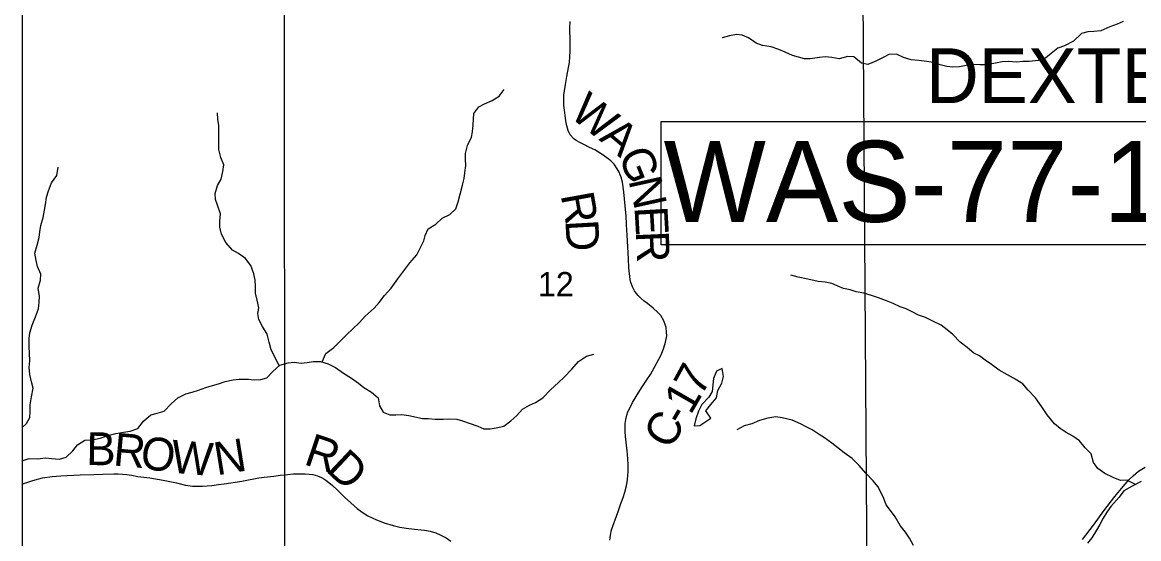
# Model space of a CAD drawing. Extents: x 0 to 34, y 0 to 22.
# Drawn here: x 2.1 to 4.027, y 17.434 to 18.326 of the extents above; entities that cross this region are included whole.
import ezdxf

# ---------------------------------------------------------------- set-up
doc = ezdxf.new("R2010")
doc.units = 0
for name, color, linetype in [('Default', 7, 'Continuous'), ('GM_X_Corporation_Text', 7, 'Continuous'), ('GM_X_County_Road', 7, 'Continuous'), ('GM_X_County_Road_Text', 7, 'Continuous'), ('GM_X_Minor_Lake', 7, 'Continuous'), ('GM_X_Minor_River', 7, 'Continuous'), ('GM_X_Rail_Line', 7, 'Continuous'), ('GM_X_Section', 7, 'Continuous'), ('GM_X_Section_Text', 7, 'Continuous'), ('GM_X_State_Route', 7, 'Continuous'), ('GM_X_Township_Road', 7, 'Continuous'), ('GM_X_Township_Road_Text', 7, 'Continuous'), ('SH_Cut_Line', 7, 'Continuous'), ('SH_Data', 7, 'Continuous')]:
    doc.layers.add(name, color=color, linetype=linetype)

msp = doc.modelspace()

# ---------------------------------------------------------------- linework, layer by layer
at = {"layer": 'Default'}
for points in [[(2.1, 18.418), (2.1, 17.4114), (2.5532, 17.3998), (2.5522, 18.4023)], [(3.2025, 18.1545), (4.5002, 18.1545), (4.5002, 17.9419), (3.2025, 17.9419)]]:
    msp.add_lwpolyline(points, close=True, dxfattribs=at)
at = {"layer": 'GM_X_County_Road'}
msp.add_lwpolyline([(3.1137, 17.4319), (3.1151, 17.4405), (3.1171, 17.4495), (3.1276, 17.4792), (3.1297, 17.4848), (3.1323, 17.4931), (3.1367, 17.5056), (3.1397, 17.5146), (3.1425, 17.5257), (3.1443, 17.5365), (3.1457, 17.5501), (3.1458, 17.562), (3.1453, 17.5724), (3.1438, 17.5859), (3.141, 17.611), (3.1403, 17.619), (3.1403, 17.6267), (3.1406, 17.6334), (3.1416, 17.6403), (3.1434, 17.6476), (3.1453, 17.6531), (3.1483, 17.6594), (3.1533, 17.6694), (3.161, 17.6829), (3.1685, 17.6949), (3.178, 17.7085), (3.1842, 17.718), (3.1913, 17.7307), (3.1985, 17.7445), (3.2029, 17.7531), (3.2071, 17.764), (3.2103, 17.7738), (3.2121, 17.7844), (3.212, 17.7911), (3.211, 17.7989), (3.2103, 17.8023), (3.2074, 17.8104), (3.2017, 17.8199), (3.1964, 17.8253), (3.1888, 17.8324), (3.1787, 17.8404), (3.173, 17.8447), (3.1679, 17.8491), (3.1629, 17.8545), (3.1596, 17.8585), (3.1567, 17.8624), (3.1536, 17.8682), (3.1504, 17.8766), (3.1491, 17.8821), (3.1469, 17.9021), (3.146, 17.9171), (3.1438, 17.9592), (3.1433, 17.9672), (3.1426, 17.9776), (3.1421, 17.9914), (3.1405, 18.009), (3.1379, 18.0335), (3.1357, 18.0502), (3.1333, 18.0586), (3.132, 18.0624), (3.13, 18.0671), (3.1268, 18.0732), (3.1212, 18.0808), (3.1155, 18.0868), (3.1089, 18.0922), (3.1009, 18.098), (3.0879, 18.1056), (3.079, 18.11), (3.0691, 18.1149), (3.0624, 18.1183), (3.0558, 18.1221), (3.0516, 18.1248), (3.0456, 18.1316), (3.0421, 18.139), (3.0395, 18.1472), (3.0379, 18.1558), (3.0355, 18.1742), (3.0347, 18.1824), (3.0343, 18.1939), (3.0347, 18.2003), (3.0356, 18.2077), (3.0373, 18.2185), (3.04, 18.2326), (3.0427, 18.248), (3.0441, 18.2568), (3.045, 18.2667), (3.0455, 18.2757), (3.0453, 18.2824), (3.0455, 18.2944), (3.0454, 18.3014), (3.0452, 18.3081), (3.0451, 18.3172), (3.0456, 18.3274)], dxfattribs=at)
at = {"layer": 'GM_X_Minor_Lake'}
for points in [[(3.2882, 17.6423), (3.2794, 17.6552), (3.2881, 17.6662), (3.298, 17.6777), (3.3006, 17.6902), (3.3073, 17.7031), (3.3103, 17.7145), (3.308, 17.7281), (3.3013, 17.725)], [(3.3013, 17.725), (3.2981, 17.7235), (3.2929, 17.711), (3.2907, 17.6882), (3.2847, 17.6784), (3.2726, 17.6662), (3.2669, 17.6544), (3.2624, 17.6415), (3.2594, 17.6289), (3.2693, 17.6297), (3.2882, 17.6423)]]:
    msp.add_lwpolyline(points, dxfattribs=at)
at = {"layer": 'GM_X_Minor_River'}
for points in [[(4.0001, 18.3273), (3.9895, 18.3227), (3.977, 18.318), (3.9615, 18.3111), (3.9493, 18.3103), (3.9387, 18.3094), (3.9277, 18.3067), (3.9141, 18.2937), (3.8986, 18.2853), (3.8869, 18.2814), (3.8759, 18.2719), (3.8657, 18.2642), (3.8532, 18.26), (3.8377, 18.2583), (3.8266, 18.2583), (3.816, 18.2574), (3.8012, 18.2585), (3.7913, 18.2577), (3.7769, 18.2549), (3.7629, 18.2525), (3.7523, 18.2525), (3.742, 18.2532), (3.7287, 18.2512), (3.7174, 18.2492), (3.706, 18.2488), (3.6957, 18.2498), (3.6839, 18.2524), (3.6717, 18.2569), (3.6611, 18.2583), (3.647, 18.2601), (3.6341, 18.2612), (3.6208, 18.2653), (3.6086, 18.2709), (3.5957, 18.2704), (3.5855, 18.265)], [(3.5855, 18.265), (3.573, 18.2589), (3.5594, 18.2531), (3.548, 18.2557), (3.535, 18.2662), (3.5247, 18.2669), (3.5096, 18.263), (3.497, 18.2652), (3.4856, 18.2663), (3.4758, 18.2655), (3.4598, 18.2627), (3.45, 18.263), (3.4393, 18.2656), (3.4294, 18.2686), (3.4165, 18.2742), (3.4054, 18.279), (3.3921, 18.2835), (3.3773, 18.2861), (3.3666, 18.2898), (3.3533, 18.2992), (3.3426, 18.304), (3.3324, 18.3047), (3.3202, 18.3028), (3.3077, 18.2993)], [(2.6172, 17.7396), (2.6239, 17.7538), (2.6378, 17.7645), (2.6472, 17.7741), (2.66, 17.7867), (2.6701, 17.7962), (2.6817, 17.8077), (2.6919, 17.8184), (2.7073, 17.8322), (2.7159, 17.8421), (2.7252, 17.854), (2.7365, 17.8669), (2.7481, 17.8833), (2.7585, 17.8971), (2.7686, 17.9104), (2.7806, 17.9246), (2.7862, 17.9348), (2.7929, 17.9485), (2.7951, 17.958), (2.8007, 17.9691), (2.8135, 17.9772), (2.8247, 17.9875), (2.8379, 17.994), (2.8481, 18.004), (2.8521, 18.0162), (2.8554, 18.0294), (2.8598, 18.0447), (2.8624, 18.0564), (2.8638, 18.0659), (2.8652, 18.0788), (2.8647, 18.0898), (2.865, 18.0997), (2.8683, 18.113), (2.8754, 18.1274), (2.8768, 18.1369), (2.8778, 18.149), (2.8785, 18.1585), (2.8795, 18.1688), (2.8878, 18.1802), (2.8979, 18.1852), (2.9111, 18.191), (2.9232, 18.1983), (2.9318, 18.2102)], [(2.543, 17.7326), (2.5346, 17.7507), (2.5292, 17.7605), (2.5261, 17.7738), (2.5226, 17.7874), (2.5145, 17.8006), (2.508, 17.813), (2.5064, 17.8229), (2.5082, 17.8331), (2.5054, 17.846), (2.5023, 17.8585), (2.5022, 17.8698), (2.5017, 17.8805), (2.4993, 17.8914), (2.4943, 17.9058), (2.4851, 17.9182), (2.4729, 17.9268), (2.4626, 17.9324), (2.4511, 17.9456), (2.4438, 17.9603), (2.4411, 17.972), (2.4406, 17.9827), (2.442, 17.9955), (2.4366, 18.0103), (2.4331, 18.0201), (2.4326, 18.0303), (2.437, 18.044), (2.443, 18.0554), (2.4463, 18.0684), (2.4477, 18.0801), (2.4427, 18.0926), (2.4391, 18.1066), (2.4389, 18.1369), (2.4391, 18.1479), (2.4375, 18.1589), (2.4367, 18.1695)], [(2.1, 17.626), (2.1072, 17.6333), (2.1128, 17.6436), (2.1138, 17.6538), (2.1137, 17.6656), (2.1159, 17.6792), (2.1188, 17.6941), (2.116, 17.7054), (2.1129, 17.7179), (2.112, 17.7296), (2.1127, 17.7414), (2.1126, 17.7547), (2.1117, 17.7656), (2.112, 17.7797), (2.113, 17.7899), (2.1167, 17.8032), (2.123, 17.8173), (2.1278, 17.831), (2.1292, 17.8427), (2.1295, 17.8526), (2.1271, 17.867), (2.1311, 17.8807), (2.1322, 17.8913), (2.1264, 17.9045), (2.1236, 17.9147), (2.1216, 17.9276), (2.1257, 17.9413), (2.1293, 17.9542), (2.13, 17.964), (2.1322, 17.9754), (2.1362, 17.9891), (2.1384, 18.0016), (2.1402, 18.0115), (2.1416, 18.024), (2.1449, 18.0351), (2.1501, 18.0487), (2.1598, 18.0613), (2.1616, 18.0761)], [(4.0214, 17.528), (4.0061, 17.5354), (3.9951, 17.5349), (3.9825, 17.5402), (3.968, 17.5469), (3.9562, 17.5555), (3.9485, 17.5657), (3.9446, 17.5809), (3.9343, 17.5914), (3.9247, 17.6035), (3.9129, 17.6114), (3.9015, 17.6174), (3.8912, 17.6245), (3.8816, 17.6328), (3.869, 17.6479), (3.8594, 17.6619), (3.8487, 17.6777), (3.8361, 17.6909), (3.8265, 17.7015), (3.8109, 17.7116), (3.8002, 17.7172), (3.7857, 17.7251), (3.7728, 17.7349), (3.7617, 17.7428), (3.7522, 17.7499), (3.7419, 17.7548), (3.7304, 17.7646), (3.7186, 17.7736), (3.706, 17.7868), (3.6964, 17.7951), (3.6857, 17.803), (3.6716, 17.8101), (3.6587, 17.8161), (3.6465, 17.8202), (3.637, 17.8254), (3.6256, 17.8314), (3.6149, 17.8344), (3.6031, 17.8407), (3.5913, 17.8452), (3.5776, 17.8504), (3.5658, 17.8545), (3.5525, 17.8582), (3.5388, 17.8604), (3.5285, 17.8641), (3.5175, 17.8663), (3.5065, 17.8712), (3.4969, 17.8749), (3.4855, 17.8775), (3.4737, 17.8786), (3.4559, 17.8826), (3.4391, 17.8859), (3.4266, 17.8893)], [(2.1, 17.5686), (2.1119, 17.5727), (2.1255, 17.5721), (2.1403, 17.5737), (2.1505, 17.5727), (2.1641, 17.5716), (2.1755, 17.5748), (2.1871, 17.5859), (2.195, 17.5962), (2.2078, 17.6042), (2.221, 17.6051), (2.2342, 17.6079), (2.2482, 17.6125), (2.2614, 17.6161), (2.2746, 17.6181), (2.2863, 17.6201), (2.2992, 17.6247), (2.3089, 17.6373), (2.3217, 17.648), (2.3326, 17.6508), (2.3447, 17.6543), (2.3571, 17.6669), (2.3684, 17.6773), (2.3819, 17.6842), (2.3932, 17.687), (2.4038, 17.6908), (2.4166, 17.6955), (2.428, 17.6986), (2.4385, 17.7014), (2.4502, 17.7056), (2.4638, 17.7088), (2.4744, 17.71), (2.4903, 17.7098), (2.5002, 17.7087), (2.5119, 17.7092), (2.5217, 17.7119), (2.5322, 17.7227), (2.5442, 17.7337), (2.5586, 17.7377), (2.5692, 17.7393), (2.5813, 17.7375), (2.5915, 17.7383), (2.6021, 17.7403), (2.6146, 17.7404), (2.6279, 17.736), (2.6404, 17.7297), (2.6545, 17.7203), (2.6682, 17.7113), (2.68, 17.7031), (2.6895, 17.6952), (2.7029, 17.687), (2.7139, 17.6776), (2.7167, 17.6636), (2.7225, 17.6527), (2.7342, 17.6482), (2.7448, 17.6479), (2.7551, 17.6488), (2.7672, 17.647), (2.7907, 17.6419), (2.8005, 17.6416), (2.8127, 17.6405), (2.8263, 17.6407), (2.838, 17.6415), (2.8501, 17.6405), (2.8596, 17.6379), (2.8714, 17.6335), (2.8862, 17.6283), (2.8965, 17.6238), (2.9074, 17.6239), (2.9176, 17.6259), (2.9312, 17.6283), (2.9433, 17.6379), (2.9534, 17.6471), (2.9632, 17.6581), (2.9752, 17.6647), (2.9854, 17.6697), (2.9982, 17.6774), (3.0117, 17.6915), (3.0252, 17.7042), (3.0353, 17.713), (3.0485, 17.7271), (3.0597, 17.7405), (3.0736, 17.7493), (3.0861, 17.7528)], [(3.6381, 17.4222), (3.6312, 17.4351), (3.6243, 17.4453), (3.6151, 17.4573), (3.6063, 17.4721), (3.5982, 17.4827), (3.591, 17.4928), (3.5871, 17.5034), (3.5825, 17.5133), (3.5767, 17.5242), (3.5683, 17.5344), (3.556, 17.5472), (3.5442, 17.5608), (3.532, 17.5725), (3.5182, 17.5826), (3.5072, 17.5909), (3.4972, 17.5992), (3.4846, 17.6082), (3.4751, 17.6142), (3.4633, 17.6225), (3.4538, 17.627), (3.4431, 17.6326), (3.4286, 17.6389), (3.4111, 17.643), (3.4005, 17.6445), (3.3865, 17.6425), (3.3724, 17.6382), (3.3588, 17.6328), (3.3459, 17.6289), (3.3334, 17.6224)], [(4.0311, 17.5329), (4.0152, 17.5248), (4.0009, 17.5171), (3.993, 17.5061), (3.9786, 17.4897), (3.9715, 17.4798), (3.9651, 17.4695), (3.9595, 17.4585), (3.9539, 17.4489), (3.946, 17.436), (3.9381, 17.4265)]]:
    msp.add_lwpolyline(points, dxfattribs=at)
at = {"layer": 'GM_X_Rail_Line'}
msp.add_lwpolyline([(2.1, 18.7171), (2.1, 14.1), (4.5781, 14.1), (4.5658, 14.9668), (4.5509, 15.5331), (4.5478, 16.582), (4.5489, 17.6578), (4.5474, 17.7028), (4.5429, 17.9404), (4.5419, 17.9684), (4.5402, 18.2851), (4.5408, 18.3763), (4.5397, 18.3961), (4.5397, 18.4045), (4.5399, 18.4424), (4.5403, 18.5054), (4.5462, 18.6416), (3.8456, 18.6615), (3.8442, 18.6615), (2.9234, 18.6945), (2.9222, 18.6946), (2.7892, 18.6993), (2.7864, 18.6994)], close=True, dxfattribs=at)
at = {"layer": 'GM_X_Section'}
msp.add_lwpolyline([(2.5522, 18.4023), (3.5508, 18.3698), (3.5573, 17.3676), (2.5532, 17.3998)], close=True, dxfattribs=at)
at = {"layer": 'GM_X_State_Route'}
msp.add_lwpolyline([(3.9295, 17.433), (3.9488, 17.4577), (3.9667, 17.4821), (3.9855, 17.5073), (3.9969, 17.5209), (4.0096, 17.5356), (4.0171, 17.5429), (4.0266, 17.5507), (4.0377, 17.5579)], dxfattribs=at)
at = {"layer": 'GM_X_Township_Road'}
msp.add_lwpolyline([(2.1, 17.5283), (2.1024, 17.5293), (2.1184, 17.535), (2.1347, 17.5393), (2.1517, 17.5418), (2.1664, 17.5429), (2.2, 17.5448), (2.2235, 17.5451), (2.2386, 17.5456), (2.2577, 17.5462), (2.2653, 17.5461), (2.2729, 17.5456), (2.2801, 17.5451), (2.2885, 17.5437), (2.2992, 17.5418), (2.32, 17.5391), (2.3428, 17.5355), (2.3658, 17.5306), (2.3818, 17.5268), (2.3937, 17.5251), (2.4107, 17.5251), (2.427, 17.5263), (2.4387, 17.5276), (2.4486, 17.5289), (2.4788, 17.5336), (2.4901, 17.5359), (2.4994, 17.5377), (2.5083, 17.5392), (2.5173, 17.5406), (2.5343, 17.5424), (2.5452, 17.5439), (2.558, 17.545), (2.5681, 17.5462), (2.5796, 17.5463), (2.588, 17.5463), (2.5951, 17.5459), (2.6015, 17.5451), (2.6095, 17.5426), (2.6161, 17.54), (2.6202, 17.5377), (2.6236, 17.5354), (2.6291, 17.5312), (2.6352, 17.5259), (2.6431, 17.5184), (2.6562, 17.5059), (2.6671, 17.496), (2.6727, 17.491), (2.6779, 17.4866), (2.6867, 17.48), (2.6961, 17.474), (2.711, 17.4667), (2.7245, 17.4617), (2.7399, 17.4571), (2.7514, 17.454), (2.7623, 17.4523), (2.7766, 17.4505), (2.7939, 17.4491), (2.8038, 17.4471), (2.8137, 17.4443), (2.8224, 17.4406), (2.8315, 17.4359), (2.8398, 17.4302)], dxfattribs=at)
at = {"layer": 'SH_Cut_Line'}
msp.add_lwpolyline([(2.1, 20.9), (2.1, 14.1), (4.5781, 14.1)], dxfattribs=at)
at = {"layer": 'SH_Data'}
msp.add_line((2.1, 20.9), (2.1, 14.1), dxfattribs=at)

# ---------------------------------------------------------------- texts
at = {"layer": 'Default'}
msp.add_text('WAS-77-17.13', height=0.14, dxfattribs=at).set_placement((3.2067, 17.9813))
at = {"layer": 'GM_X_Corporation_Text'}
msp.add_text('DEXTER CITY', height=0.094697, rotation=0, dxfattribs=at).set_placement((3.6593, 18.1865))
at = {"layer": 'GM_X_County_Road_Text'}
for s, rotation, p in [('W', 321.631, (3.0426, 18.1642)), ('A', 319.8871, (3.0938, 18.1236)), ('G', 292.1295, (3.1278, 18.0972)), ('N', 282.4652, (3.1459, 18.0533)), ('R', 280.2612, (3.029, 18.0279)), ('E', 273.2761, (3.1564, 18.0069)), ('D', 273.2512, (3.0371, 17.9838)), ('R', 272.4792, (3.1588, 17.9647)), ('7', 61.4482, (3.2715, 17.6782)), ('1', 60.1638, (3.2534, 17.6466)), ('C', 59.7739, (3.218, 17.5858)), ('-', 59.8528, (3.2415, 17.6262))]:
    msp.add_text(s, height=0.0568, rotation=rotation, dxfattribs=at).set_placement(p)
at = {"layer": 'GM_X_Section_Text'}
msp.add_text('12', height=0.04186, rotation=0, dxfattribs=at).set_placement((2.9895, 17.8529))
at = {"layer": 'GM_X_Township_Road_Text'}
for s, rotation, p in [('B', 359.1374, (2.2101, 17.5615)), ('R', 354.79, (2.2556, 17.5609)), ('O', 351.1419, (2.3012, 17.5567)), ('R', 341.3392, (2.5839, 17.5633)), ('W', 355.136, (2.3549, 17.5485)), ('N', 9.173, (2.4356, 17.5435)), ('D', 316.7003, (2.6226, 17.5517))]:
    msp.add_text(s, height=0.0568, rotation=rotation, dxfattribs=at).set_placement(p)

doc.saveas('drawing.dxf')
